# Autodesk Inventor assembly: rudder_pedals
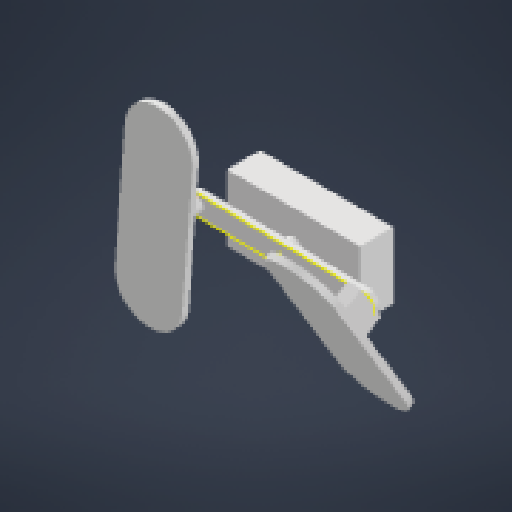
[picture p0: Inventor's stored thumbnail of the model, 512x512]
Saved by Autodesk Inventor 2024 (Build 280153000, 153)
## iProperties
Created: 2023-09
Part Number: rudder_pedals
Document SubType Name: Assembly
Designer: mammothbane
Author: mammothbane
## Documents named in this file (5)
- \\caemlyn.p.hs.npry.dev\media\modeling\mit\mas.863\rudder_pedals.iam
- \\caemlyn.p.hs.npry.dev\media\modeling\mit\mas.863\rp_base.ipt
- \\caemlyn.p.hs.npry.dev\media\modeling\mit\mas.863\rp_pedal.ipt
- \\caemlyn.p.hs.npry.dev\media\modeling\mit\mas.863\rp_arm.ipt
- \\caemlyn.p.hs.npry.dev\media\modeling\mit\mas.863\pedal_joint.ipt
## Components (6 placed, 4 different names)
1. rp_base:1 — Flush:1, Rotational:2
2. rp_pedal:1 — Rotational:3
3. rp_arm:1 — Flush:1, Flush:3, Rotational:1, Rotational:2, Rotational:4
4. pedal_joint:1 — Flush:3, Rotational:1, Rotational:3
5. rp_pedal:2 — Rotational:5
6. pedal_joint:2 — Rotational:4, Rotational:5
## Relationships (7: RevoluteJoint 5, Flush 2)
- Flush:1: rp_base:1 ↔ rp_arm:1
- Flush:3: rp_arm:1 ↔ pedal_joint:1
- Rotational:1 [RevoluteJoint]: rp_arm:1 ↔ pedal_joint:1
- Rotational:2 [RevoluteJoint]: rp_base:1 ↔ rp_arm:1
- Rotational:3 [RevoluteJoint]: rp_pedal:1 ↔ pedal_joint:1
- Rotational:4 [RevoluteJoint]: rp_arm:1 ↔ pedal_joint:2
- Rotational:5 [RevoluteJoint]: rp_pedal:2 ↔ pedal_joint:2
